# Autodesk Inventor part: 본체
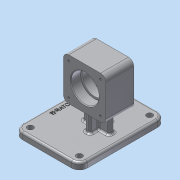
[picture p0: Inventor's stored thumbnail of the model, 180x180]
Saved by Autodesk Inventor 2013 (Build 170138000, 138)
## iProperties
Created: 2020-11
Part Number: 본체
Material: 알루미늄 6061
Document SubType Name: Modeling
Designer: Administrator
Density: 2.71 g/cm^3
Mass: 685.609 g
Surface Area: 543.155 cm^2
Volume: 252.992 cm^3
Author: Administrator
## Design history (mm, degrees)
sketch "스케치1"
  geometry: L1 (-65, 49)-(65, 49); L2 (65, 49)-(65, -49); L3 (65, -49)-(-65, -49); L4 (-65, -49)-(-65, 49); L5 (-65, 49)-(65, -49); L6 (65, 49)-(-65, -49); 1 further point
  constraints: 12 end point, 2 midpoint, 2 parallel, 1 horizontal, 1 perpendicular
  dimensions: "d0" = 130 distance of L1.start L1.end; "d2" = 98 distance of L1.end L2.end
extrude "돌출1" new body sketch "스케치1" distance "d3" = 10; taper "d4" = 0 deg
sketch "스케치3"
  geometry: L1 (-19, 102)-(45, 102); L2 (45, 102)-(45, 38); L3 (45, 38)-(-19, 38); L4 (-19, 38)-(-19, 102); L5 (-19, 102)-(45, 38); L6 (45, 102)-(-19, 38); L7 (-49, 0)-(49, 0) reference; L8 (-49, 0)-(-49, 10) reference; 2 further points
  constraints: 12 end point, 2 midpoint, 2 parallel, 2 perpendicular, 1 horizontal
  dimensions: "d12" = 64 distance of L2.end L3.end; "d14" = 70 distance from line of L7 point (13, 70); "d15" = 62 distance from line of point (13, 70) L8
extrude "돌출3" join sketch "스케치3" stored distance "d16" = 42; taper "d17" = 0 deg
sketch "스케치4"
  geometry: L1 (-38, -19)-(-38, 45) reference; L2 (0, 49)-(0, -49) reference; C1 r 18 at (-70, 13); 2 further points
  constraints: 1 centre point, 1 horizontal alignment, 1 midpoint
  dimensions: "d18" = 70 distance from line of L2 C1.centre; "d19" = 36 diameter of C1
extrude "돌출4" cut sketch "스케치4" distance "d20" = 42; taper "d21" = 0 deg
hole "구멍1" diameter "d24" = 42; stored, may be unused: countersink angle "d28" = 90 deg, drill point angle "d30" = 0 deg; dims "d25" = 6, "d26" = 4, "d27" = 2, "d29" = 15, "d56" = 10, "d57" = 10
fillet "모깎기1" dims "d31" = 8
sketch "스케치5"
  geometry: L1 (37, 38)-(-11, 38) reference; L2 (49, 10)-(-49, 10) reference; L3 (-7, 40.585)-(33, 40.585); L4 (33, 40.585)-(33, 5.169); L5 (33, 5.169)-(-7, 5.169); L6 (-7, 5.169)-(-7, 40.585); L7 (-49, 0)-(49, 0) reference; 3 further points
  constraints: 8 end point, 2 midpoint, 2 parallel, 1 horizontal, 1 perpendicular, 1 vertical alignment
  dimensions: "d32" = 40 distance of L4.end L5.end; "d34" = 5.16861 distance between parallel lines of L7 L5; "d35" = 35.41667 distance of L5.end L3.start
extrude "돌출5" join sketch "스케치5" stored distance "d36" = 8; taper "d37" = 0 deg
node "작업 평면4"
  node "작업 평면3"
sketch "스케치6"
  geometry: L1 (-86, -38)-(-44, -38) reference; L2 (-48, -45.334)-(-82, -45.334); L3 (-82, -45.334)-(-82, -5.334); L4 (-82, -5.334)-(-48, -5.334); L5 (-48, -5.334)-(-48, -45.334); L6 (0, 0)-(-130, 0) reference; 3 further points
  constraints: 8 end point, 2 midpoint, 2 parallel, 1 horizontal, 1 perpendicular, 1 vertical alignment
  dimensions: "d39" = 34 distance of L3.end L4.end; "d41" = 5.33397 distance between parallel lines of L6 L4; "d42" = 40 distance of L4.end L2.start
extrude "돌출6" join sketch "스케치6" stored distance "d43" = 8; taper "d44" = 0 deg
chamfer "모따기1" distance "d45" = 1; stored, may be unused: second distance "d46" = 2, angle "d47" = 45 deg
fillet "모깎기2" dims "d48" = 0.3
sketch "스케치7"
  geometry: A1 r 8 centre (-94, -11) between (-102, -11) and (-94, -19) reference; 2 further points
  constraints: 1 coincident
hole "구멍2" sketch "스케치7" at (-94, -11) diameter "d49" = 3.242; stored, may be unused: countersink angle "d53" = 90 deg, drill point angle "d55" = 118 deg; dims "d50" = 8, "d51" = 4, "d52" = 2, "d54" = 10
fillet "모깎기3" dims "d64" = 3
fillet "모깎기4" dims "d65" = 3
fillet "모깎기5" dims "d66" = 12
fillet "모깎기6" dims "d67" = 3
hole "구멍3" diameter "d70" = 9; stored, may be unused: countersink angle "d74" = 90 deg, drill point angle "d76" = 0 deg; dims "d68" = 10, "d69" = 10, "d71" = 8, "d72" = 4, "d73" = 2, "d75" = 10
hole "구멍4" diameter "d79" = 9; stored, may be unused: countersink angle "d83" = 90 deg, drill point angle "d85" = 0 deg; dims "d77" = 10, "d78" = 10, "d80" = 8, "d81" = 4, "d82" = 2, "d84" = 10
hole "구멍5" diameter "d88" = 9; stored, may be unused: countersink angle "d92" = 90 deg, drill point angle "d94" = 0 deg; dims "d86" = 10, "d87" = 10, "d89" = 8, "d90" = 4, "d91" = 2, "d93" = 10
hole "구멍6" diameter "d97" = 9; stored, may be unused: countersink angle "d101" = 90 deg, drill point angle "d103" = 0 deg; dims "d95" = 10, "d96" = 10, "d98" = 8, "d99" = 4, "d100" = 2, "d102" = 10
sketch "스케치8"
  geometry: L1 (-53, -49)-(53, -49) reference; L2 (-65, 37)-(-65, -37) reference; 2 further points
  constraints: 1 other
  dimensions: "d106" = 10 distance from line of L1 point (0, -39); "d107" = 65 distance from line of L2 point (0, -39)
feature "엠보싱1" sketch "스케치8" dims "d0" = 130, "d2" = 98, "d108" = 0.5, "d109" = 0
node "솔리드1"
mirror "대칭1"
pattern_linear "직사각형 패턴1" dims "d60" = 48, "d63" = 48
mirror "대칭2"
other parameters: "d38" = -36
